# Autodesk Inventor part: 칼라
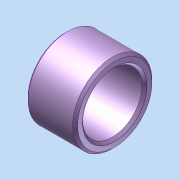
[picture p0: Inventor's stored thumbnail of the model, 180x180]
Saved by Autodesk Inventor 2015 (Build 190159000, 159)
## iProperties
Created: 2024-06
Part Number: 칼라
Material: 일반
Document SubType Name: Modeling
Designer: Administrator
Density: 1 g/cm^3
Appearance: 기본값
Author: Administrator
Author: jhkim
Creation Date: 2024-05-29
Sending System: Autodesk Inventor 2025
Preprocessor: ST-DEVELOPER v20
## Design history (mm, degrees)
node "칼라1"
node "솔리드1"
node "기준1"
